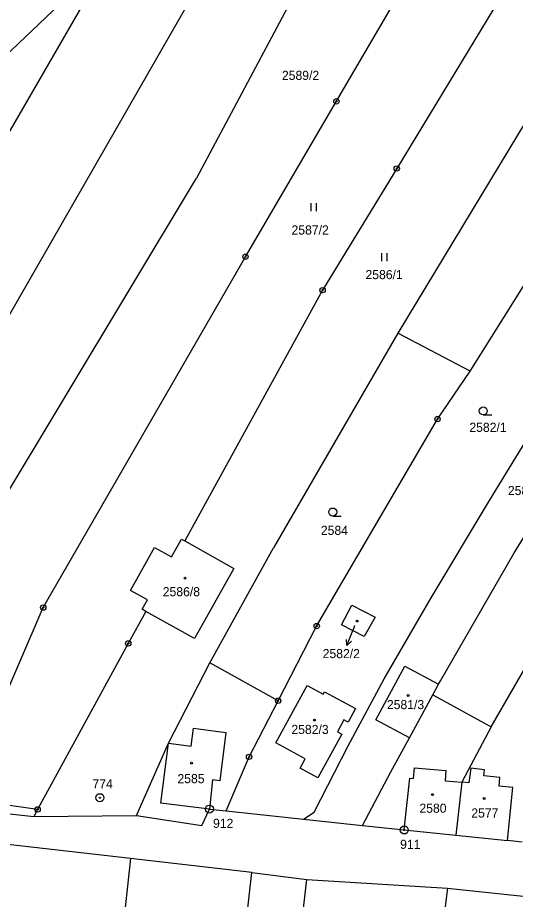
# Model space of a CAD drawing. Extents: x -755819 to -753140, y -1169796 to -1166000.
# Drawn here: x -754587.3 to -754494.4, y -1168949.3 to -1168784.9 of the extents above; entities that cross this region are included whole.
import ezdxf

# ---------------------------------------------------------------- set-up
doc = ezdxf.new("R2010")
doc.units = 0
for name, color, linetype in [('Vrstva 1', 7, 'Continuous'), ('Vrstva 12', 7, 'Continuous'), ('Vrstva 16', 7, 'Continuous'), ('Vrstva 17', 7, 'Continuous'), ('Vrstva 18', 7, 'Continuous'), ('Vrstva 19', 7, 'Continuous'), ('Vrstva 24', 7, 'Continuous'), ('Vrstva 25', 7, 'Continuous'), ('Vrstva 4', 7, 'Continuous'), ('Vrstva 6', 7, 'Continuous')]:
    doc.layers.add(name, color=color, linetype=linetype)

msp = doc.modelspace()

# ---------------------------------------------------------------- linework, layer by layer
at = {"layer": 'Vrstva 1'}
for p, q in [((-754527.76, -1168800.47), (-754468.68, -1168699.59)), ((-754457.95, -1168716.5), (-754516.5, -1168813)), ((-754590.22, -1168808.64), (-754542.2, -1168725.58)), ((-754451.95, -1168737.18), (-754516.29, -1168843.7)), ((-754502.8, -1168850.81), (-754446.52, -1168760.99)), ((-754530.89, -1168771.74), (-754553.88, -1168814.82)), ((-754544.73, -1168829.46), (-754527.76, -1168800.47)), ((-754516.5, -1168813), (-754530.35, -1168835.7)), ((-754598.31, -1168888.72), (-754553.88, -1168814.82)), ((-754582.46, -1168894.9), (-754544.73, -1168829.46)), ((-754530.35, -1168835.7), (-754556.08, -1168882.48)), ((-754516.29, -1168843.7), (-754531.57, -1168870.04)), ((-754502.8, -1168850.81), (-754516.29, -1168843.7)), ((-754508.9, -1168859.75), (-754502.8, -1168850.81)), ((-754499.2, -1168874.96), (-754488.24, -1168856.95)), ((-754531.45, -1168898.35), (-754508.9, -1168859.75)), ((-754494.64, -1168884.83), (-754480.34, -1168861.35)), ((-754531.57, -1168870.04), (-754539.52, -1168883.73)), ((-754510.07, -1168893.09), (-754499.2, -1168874.96)), ((-754558.55, -1168885.44), (-754556.7, -1168882.13)), ((-754556.7, -1168882.13), (-754556.08, -1168882.48)), ((-754566.2, -1168891.72), (-754561.7, -1168883.68)), ((-754561.7, -1168883.68), (-754558.55, -1168885.44)), ((-754556.08, -1168882.48), (-754546.93, -1168887.6)), ((-754551.4, -1168905.2), (-754539.52, -1168883.73)), ((-754508.35, -1168908.57), (-754494.64, -1168884.83)), ((-754546.93, -1168887.6), (-754554.23, -1168900.66)), ((-754563.03, -1168893.47), (-754566.2, -1168891.72)), ((-754564.01, -1168895.23), (-754563.03, -1168893.47)), ((-754518.84, -1168908.22), (-754510.07, -1168893.09)), ((-754597.88, -1168930.55), (-754582.46, -1168894.9)), ((-754563.31, -1168895.62), (-754564.01, -1168895.23)), ((-754526.81, -1168898.15), (-754524.89, -1168894.44)), ((-754524.89, -1168894.44), (-754520.53, -1168896.7)), ((-754563.31, -1168895.62), (-754566.6, -1168901.6)), ((-754554.23, -1168900.66), (-754563.31, -1168895.62)), ((-754520.53, -1168896.7), (-754522.6, -1168900.32)), ((-754538.63, -1168912.29), (-754531.45, -1168898.35)), ((-754522.6, -1168900.32), (-754526.81, -1168898.15)), ((-754498.86, -1168917.13), (-754489.07, -1168900.09)), ((-754566.6, -1168901.6), (-754583.52, -1168932.56)), ((-754559.12, -1168920.21), (-754551.4, -1168905.2)), ((-754538.63, -1168912.29), (-754551.4, -1168905.2)), ((-754520.41, -1168915.82), (-754514.97, -1168905.81)), ((-754514.97, -1168905.81), (-754508.7, -1168909.21)), ((-754525.57, -1168920.67), (-754518.84, -1168908.22)), ((-754539.05, -1168920.16), (-754533.24, -1168909.43)), ((-754533.24, -1168909.43), (-754530.23, -1168911.05)), ((-754509.79, -1168911.21), (-754508.7, -1168909.21)), ((-754508.7, -1168909.21), (-754508.35, -1168908.57)), ((-754530.23, -1168911.05), (-754529.99, -1168910.61)), ((-754529.99, -1168910.61), (-754524.21, -1168913.76)), ((-754514.15, -1168919.23), (-754509.79, -1168911.21)), ((-754509.79, -1168911.21), (-754498.86, -1168917.13)), ((-754544.06, -1168922.75), (-754538.63, -1168912.29)), ((-754524.21, -1168913.76), (-754525.57, -1168916.3)), ((-754526.36, -1168915.87), (-754527.55, -1168918.08)), ((-754525.57, -1168916.3), (-754526.36, -1168915.87)), ((-754514.15, -1168919.23), (-754520.41, -1168915.82)), ((-754527.55, -1168918.08), (-754526.76, -1168918.51)), ((-754498.86, -1168917.13), (-754504.37, -1168927.48)), ((-754526.76, -1168918.51), (-754531.22, -1168926.68)), ((-754517.6, -1168925.57), (-754514.15, -1168919.23)), ((-754565.1, -1168933.7), (-754559.12, -1168920.21)), ((-754533.6, -1168923.11), (-754539.05, -1168920.16)), ((-754531.94, -1168933.04), (-754525.57, -1168920.67)), ((-754548.33, -1168932.84), (-754544.06, -1168922.75)), ((-754534.55, -1168924.87), (-754533.6, -1168923.11)), ((-754531.22, -1168926.68), (-754534.55, -1168924.87)), ((-754502.7, -1168924.89), (-754503.03, -1168927.62)), ((-754500.13, -1168925.16), (-754502.7, -1168924.89)), ((-754522.87, -1168935.54), (-754517.6, -1168925.57)), ((-754500.25, -1168926.3), (-754500.13, -1168925.16)), ((-754497.24, -1168926.61), (-754500.25, -1168926.3)), ((-754504.37, -1168927.48), (-754505.5, -1168937.33)), ((-754503.03, -1168927.62), (-754504.37, -1168927.48)), ((-754497.41, -1168928.21), (-754497.24, -1168926.61)), ((-754494.81, -1168928.48), (-754497.41, -1168928.21)), ((-754495.85, -1168938.33), (-754494.81, -1168928.48)), ((-754583.52, -1168932.56), (-754597.88, -1168930.55)), ((-754598.62, -1168932.27), (-754584.25, -1168933.9)), ((-754583.52, -1168932.56), (-754584.25, -1168933.9)), ((-754552.85, -1168935.56), (-754551.47, -1168932.5)), ((-754551.47, -1168932.5), (-754548.33, -1168932.84)), ((-754548.33, -1168932.84), (-754536.75, -1168934.07)), ((-754533.91, -1168934.38), (-754531.94, -1168933.04)), ((-754584.25, -1168933.9), (-754565.1, -1168933.7)), ((-754565.1, -1168933.7), (-754552.85, -1168935.56)), ((-754536.75, -1168934.07), (-754533.91, -1168934.38)), ((-754533.91, -1168934.38), (-754522.87, -1168935.54)), ((-754522.87, -1168935.54), (-754515.1, -1168936.39)), ((-754515.1, -1168936.39), (-754505.5, -1168937.33)), ((-754505.5, -1168937.33), (-754495.85, -1168938.33)), ((-754566.16, -1168941.72), (-754589.1, -1168939.1)), ((-754493.09, -1168938.67), (-754495.85, -1168938.33)), ((-754566.16, -1168941.72), (-754572.49, -1168997.06)), ((-754543.55, -1168944.3), (-754566.16, -1168941.72)), ((-754549.49, -1168998), (-754543.55, -1168944.3)), ((-754543.55, -1168944.3), (-754533.27, -1168945.61)), ((-754537.21, -1168980.26), (-754533.27, -1168945.61)), ((-754533.27, -1168945.61), (-754507.06, -1168947.27)), ((-754507.06, -1168947.27), (-754511.28, -1168981.74)), ((-754507.06, -1168947.27), (-754481.59, -1168949.91))]:
    msp.add_line(p, q, dxfattribs=at)
at = {"layer": 'Vrstva 12'}
msp.add_line((-754561.35, -1168765.15), (-754645.34, -1168845.03), dxfattribs=at)
at = {"layer": 'Vrstva 16'}
for p in [(-754524.37, -1168898.33), (-754525.81, -1168901.95)]:
    msp.add_line(p, (-754524.7, -1168899.16), dxfattribs=at)
msp.add_lwpolyline([(-754524.97, -1168901.2), (-754525.81, -1168901.95), (-754525.9, -1168900.83)], dxfattribs=at)
at = {"layer": 'Vrstva 24'}
for centre, radius in [((-754527.76, -1168800.47), 0.5), ((-754527.76, -1168800.47), 0.1), ((-754516.5, -1168813), 0.5), ((-754516.5, -1168813), 0.1), ((-754544.73, -1168829.46), 0.5), ((-754544.73, -1168829.46), 0.1), ((-754530.35, -1168835.7), 0.5), ((-754530.35, -1168835.7), 0.1), ((-754508.9, -1168859.75), 0.5), ((-754508.9, -1168859.75), 0.1), ((-754582.46, -1168894.9), 0.5), ((-754582.46, -1168894.9), 0.1), ((-754531.45, -1168898.35), 0.5), ((-754531.45, -1168898.35), 0.1), ((-754566.6, -1168901.6), 0.5), ((-754566.6, -1168901.6), 0.1), ((-754538.63, -1168912.29), 0.5), ((-754538.63, -1168912.29), 0.1), ((-754544.06, -1168922.75), 0.5), ((-754544.06, -1168922.75), 0.1), ((-754571.91, -1168930.37), 0.75), ((-754571.91, -1168930.37), 0.1), ((-754583.52, -1168932.56), 0.5), ((-754583.52, -1168932.56), 0.1), ((-754551.47, -1168932.5), 0.75), ((-754551.47, -1168932.5), 0.1), ((-754515.1, -1168936.39), 0.75), ((-754515.1, -1168936.39), 0.1)]:
    msp.add_circle(centre, radius, dxfattribs=at)
at = {"layer": 'Vrstva 25'}
for p, q in [((-754532.46, -1168820.96), (-754532.46, -1168819.46)), ((-754531.46, -1168820.96), (-754531.46, -1168819.46)), ((-754519.31, -1168830.29), (-754519.31, -1168828.79)), ((-754518.31, -1168830.29), (-754518.31, -1168828.79)), ((-754500.36, -1168858.97), (-754498.76, -1168858.97)), ((-754528.45, -1168877.83), (-754526.85, -1168877.83))]:
    msp.add_line(p, q, dxfattribs=at)
for centre, radius in [((-754500.36, -1168858.22), 0.75), ((-754528.45, -1168877.08), 0.75), ((-754556.02, -1168889.42), 0.175), ((-754523.89, -1168897.41), 0.175), ((-754514.37, -1168911.31), 0.175), ((-754531.83, -1168915.88), 0.175), ((-754554.82, -1168923.93), 0.175), ((-754509.85, -1168929.8), 0.175), ((-754500.17, -1168930.51), 0.175)]:
    msp.add_circle(centre, radius, dxfattribs=at)
at = {"layer": 'Vrstva 4'}
for p, q in [((-754554.87, -1168920.73), (-754554.46, -1168917.38)), ((-754554.46, -1168917.38), (-754548.39, -1168918.2)), ((-754548.39, -1168918.2), (-754549.5, -1168927.21)), ((-754560.51, -1168931.37), (-754559.12, -1168920.21)), ((-754559.12, -1168920.21), (-754554.87, -1168920.73)), ((-754513.36, -1168926.78), (-754513.2, -1168924.82)), ((-754513.2, -1168924.82), (-754507.32, -1168925.29)), ((-754507.32, -1168925.29), (-754507.47, -1168927.24)), ((-754550.87, -1168927.04), (-754551.47, -1168932.5)), ((-754549.5, -1168927.21), (-754550.87, -1168927.04)), ((-754515.1, -1168936.39), (-754514.08, -1168926.72)), ((-754514.08, -1168926.72), (-754513.36, -1168926.78)), ((-754507.47, -1168927.24), (-754504.37, -1168927.48)), ((-754551.47, -1168932.5), (-754560.51, -1168931.37))]:
    msp.add_line(p, q, dxfattribs=at)
at = {"layer": 'Vrstva 6'}
msp.add_line((-754545.24, -1168764.39), (-754611.88, -1168880.45), dxfattribs=at)

# ---------------------------------------------------------------- texts
at = {"layer": 'Vrstva 16'}
msp.add_text('2582/2', height=1.7, dxfattribs=at).set_placement((-754530.33, -1168904.34))
at = {"layer": 'Vrstva 17'}
for s, p in [('774', (-754573.28, -1168928.62)), ('912', (-754550.79, -1168936)), ('911', (-754515.87, -1168939.92))]:
    msp.add_text(s, height=1.7, dxfattribs=at).set_placement(p)
at = {"layer": 'Vrstva 18'}
for s, p in [('2589/2', (-754537.93, -1168796.48)), ('2587/2', (-754536.14, -1168825.32)), ('2586/1', (-754522.34, -1168833.64)), ('2582/1', (-754502.95, -1168862.13)), ('2581/1', (-754495.76, -1168873.92)), ('2584', (-754530.66, -1168881.35))]:
    msp.add_text(s, height=1.7, dxfattribs=at).set_placement(p)
at = {"layer": 'Vrstva 19'}
for s, height, p in [('2586/8', 1.7, (-754560.17, -1168892.79)), ('2582/2', 0.1, (-754524.63, -1168898.33)), ('2581/3', 1.7, (-754518.34, -1168913.85)), ('2582/3', 1.7, (-754536.17, -1168918.49)), ('2585', 1.7, (-754557.43, -1168927.66)), ('2580', 1.7, (-754512.27, -1168933.18)), ('2577', 1.7, (-754502.59, -1168934.07))]:
    msp.add_text(s, height=height, dxfattribs=at).set_placement(p)

doc.saveas('drawing.dxf')
